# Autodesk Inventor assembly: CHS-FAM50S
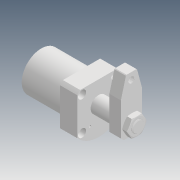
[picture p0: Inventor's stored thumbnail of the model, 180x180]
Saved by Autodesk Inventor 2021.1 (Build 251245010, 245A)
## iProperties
Created: 2019-04
Part Number: CHS-FAM50S
Description: STEP AP203
Document SubType Name: Assembly
Designer: user
Title: chs-fam50s_asm.STEP
Revision Number: ÈÎºÎ
Sending System: SolidWorks 2017
Preprocessor: SwSTEP 2.0
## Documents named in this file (6)
- D:\Vault_2016\Projekty\Clamptek\Hydraulic\CHS\CHS-50\Inventor\CHS-FAM50S\CHS-FAM50S.iam
- D:\Vault_2016\Projekty\Clamptek\Hydraulic\CHS\CHS-50\Inventor\CHS-FAM50S\CHS-FAM50BT.ipt
- D:\Vault_2016\Projekty\Clamptek\Hydraulic\CHS\CHS-50\Inventor\CHS-FAM50S\CHS-50SHSG_2.ipt
- D:\Vault_2016\Projekty\Clamptek\Hydraulic\CHS\CHS-50\Inventor\CHS-FAM50S\M6.ipt
- D:\Vault_2016\Projekty\Clamptek\Hydraulic\CHS\CHS-50\Inventor\CHS-FAM50S\CHS-50SYB_2.ipt
- D:\Vault_2016\Projekty\Clamptek\Hydraulic\CHS\CHS-50\Inventor\CHS-FAM50S\M20LM_2.ipt
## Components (8 placed, 8 different names)
1. CHS-FAM50BT_1
2. CHS-50SHSG_2_2
3. M6_3
4. M6_4
5. M6_5
6. M6_6
7. CHS-50SYB_2_7
8. M20LM_2_8
